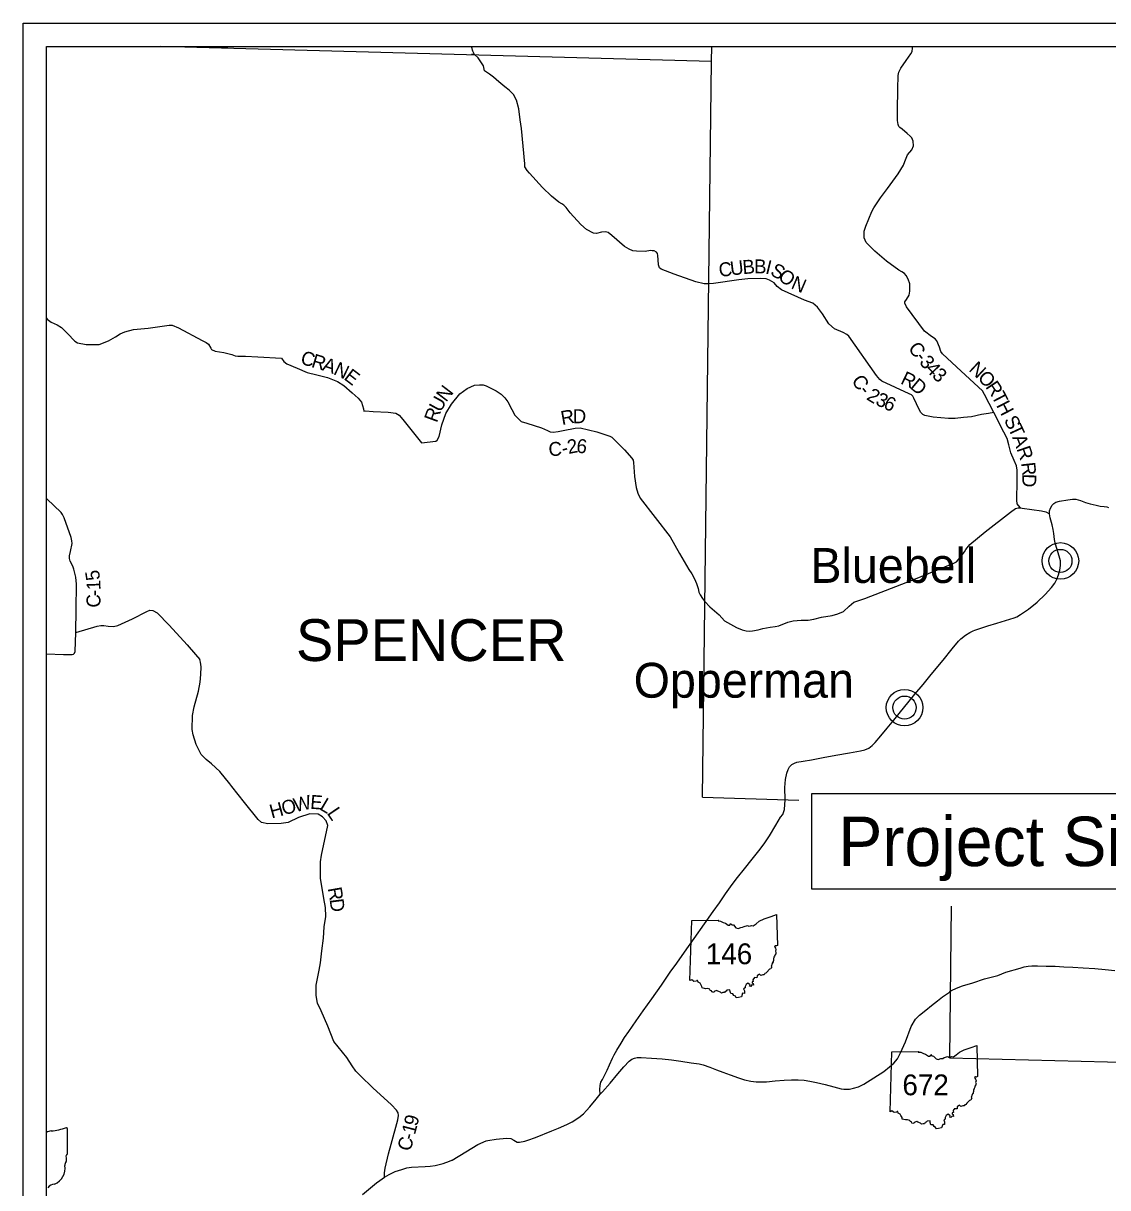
# Model space of a CAD drawing. Extents: x -452339 to 6403467, y -1 to 1814750.
# Drawn here: x -91226 to -67891, y 1630757 to 1655812 of the extents above; entities that cross this region are included whole.
import ezdxf

# ---------------------------------------------------------------- set-up
doc = ezdxf.new("R2010")
doc.units = 0
for name, color, linetype in [('Default', 7, 'Continuous'), ('GM_X_Adjacent_County_Text', 7, 'Continuous'), ('GM_X_County', 7, 'Continuous'), ('GM_X_County_Road', 7, 'Continuous'), ('GM_X_County_Road_Text', 7, 'Continuous'), ('GM_X_Section', 7, 'Continuous'), ('GM_X_Section_Text', 7, 'Continuous'), ('GM_X_Township_Road', 7, 'Continuous'), ('GM_X_Township_ROW', 7, 'Continuous'), ('GM_X_Township_Subdivision_Text', 7, 'Continuous')]:
    doc.layers.add(name, color=color, linetype=linetype)

msp = doc.modelspace()

# ---------------------------------------------------------------- linework, layer by layer
at = {"layer": 'Default'}
for p, q in [((-90726, 1655312), (-33348, 1655312)), ((-90726, 1597935), (-90726, 1655312)), ((-76880, 1635212), (-76838, 1636504)), ((-72575, 1632392), (-72533, 1633683))]:
    msp.add_line(p, q, dxfattribs=at)
msp.add_lwpolyline([(-91226, 1655812), (-32848, 1655812), (-32848, 1597435), (-91226, 1597435)], close=True, dxfattribs=at)
for points in [[(-76568, 1650204), (-76575, 1650204), (-76756, 1650252), (-77222, 1650415), (-77502, 1650519), (-77534, 1650553), (-77558, 1650617), (-77565, 1650721), (-77571, 1650817), (-77581, 1650857), (-77599, 1650889), (-77647, 1650914), (-77692, 1650918), (-77733, 1650920), (-77841, 1650900), (-78030, 1650907), (-78108, 1650917), (-78190, 1650950), (-78287, 1651008), (-78564, 1651243), (-78640, 1651312), (-78698, 1651326), (-78784, 1651318), (-78890, 1651290), (-78957, 1651299), (-79105, 1651373), (-79230, 1651484), (-79461, 1651733), (-79547, 1651845), (-79591, 1651896), (-79637, 1651930), (-79699, 1651962), (-79858, 1652094), (-80055, 1652282), (-80334, 1652589), (-80384, 1652644), (-80431, 1652724), (-80437, 1652786), (-80508, 1653547), (-80535, 1653738), (-80565, 1653970), (-80614, 1654155), (-80680, 1654279), (-80771, 1654370), (-80865, 1654444), (-80993, 1654549), (-81108, 1654653), (-81192, 1654720), (-81301, 1654788), (-81323, 1654893), (-81363, 1654963), (-81437, 1655072), (-81514, 1655141), (-81552, 1655212), (-81559, 1655236)], [(-73135, 1651262), (-73129, 1651340), (-73096, 1651448), (-72968, 1651760), (-72926, 1651840), (-72777, 1652055), (-72627, 1652257), (-72399, 1652572), (-72286, 1652758), (-72258, 1652838), (-72196, 1652983), (-72108, 1653091), (-72073, 1653173), (-72079, 1653275), (-72107, 1653345), (-72143, 1653381), (-72204, 1653440), (-72316, 1653532), (-72367, 1653570), (-72387, 1653588), (-72403, 1653633), (-72411, 1653717), (-72411, 1653933), (-72410, 1654405), (-72400, 1654689), (-72385, 1654761), (-72343, 1654847), (-72229, 1655011), (-72125, 1655156), (-72101, 1655206), (-72092, 1655276), (-72093, 1655312)], [(-69769, 1645384), (-69814, 1645433), (-69838, 1645471), (-69850, 1645551), (-69836, 1645967), (-69838, 1646197), (-69853, 1646289), (-69905, 1646403), (-69978, 1646571), (-70017, 1646742), (-70055, 1646876), (-70126, 1647012), (-70344, 1647439), (-70546, 1647828), (-70582, 1647900), (-70669, 1647980), (-71146, 1648418), (-71448, 1648699), (-71482, 1648753), (-71510, 1648842), (-71569, 1648982), (-71601, 1649020), (-71681, 1649072), (-71830, 1649189), (-72223, 1649710), (-72260, 1649793), (-72258, 1649819), (-72218, 1649872), (-72166, 1649964), (-72152, 1650050), (-72148, 1650118), (-72149, 1650206), (-72183, 1650308), (-72229, 1650385), (-72262, 1650427), (-72318, 1650467), (-72386, 1650503), (-72654, 1650694), (-72905, 1650909), (-73090, 1651096), (-73131, 1651194), (-73135, 1651262)], [(-70344, 1647439), (-70458, 1647417), (-70609, 1647392), (-70823, 1647345), (-70995, 1647327), (-71174, 1647308), (-71316, 1647311), (-71647, 1647336), (-71824, 1647372), (-71866, 1647393), (-71918, 1647447), (-72003, 1647625), (-72060, 1647743), (-72086, 1647788), (-72112, 1647814), (-72160, 1647840), (-72753, 1648112), (-72797, 1648148), (-72866, 1648237), (-73460, 1649081), (-73507, 1649119), (-73587, 1649157), (-73770, 1649238), (-73889, 1649347), (-74026, 1649563), (-74136, 1649706), (-74233, 1649790), (-74418, 1649857), (-74910, 1650080), (-75006, 1650148), (-75068, 1650225), (-75166, 1650285), (-75243, 1650311), (-75371, 1650323), (-75635, 1650314), (-75831, 1650293), (-76371, 1650216), (-76478, 1650204), (-76568, 1650204)], [(-90726, 1649464), (-90712, 1649446), (-90626, 1649379), (-90500, 1649321), (-90403, 1649266), (-90273, 1649138), (-90114, 1648969), (-90058, 1648937), (-89870, 1648899), (-89594, 1648904), (-89391, 1648977), (-89238, 1649064), (-89138, 1649127), (-89043, 1649170), (-88852, 1649221), (-88540, 1649251), (-88087, 1649317), (-88024, 1649314), (-87885, 1649257), (-87380, 1648987), (-87290, 1648944), (-87240, 1648908), (-87193, 1648824), (-87177, 1648794), (-87099, 1648760), (-86911, 1648727), (-86739, 1648682), (-86663, 1648655), (-86609, 1648651), (-86447, 1648648), (-86180, 1648636), (-85668, 1648603), (-85616, 1648537), (-85552, 1648485), (-85333, 1648390), (-85117, 1648299), (-84911, 1648248), (-84677, 1648190), (-84465, 1648105), (-84328, 1648018), (-84146, 1647860), (-84023, 1647745), (-83951, 1647657), (-83902, 1647515), (-83901, 1647465), (-83861, 1647470), (-83700, 1647458), (-83376, 1647444), (-83210, 1647421), (-83134, 1647380), (-83057, 1647284), (-82657, 1646782), (-82349, 1646823), (-82318, 1646842), (-82280, 1646924), (-82218, 1647169), (-82132, 1647419), (-82015, 1647616), (-81833, 1647840), (-81672, 1647957), (-81513, 1648022), (-81410, 1648034), (-81330, 1648034), (-81264, 1648014), (-81053, 1647905), (-80943, 1647832), (-80867, 1647756), (-80802, 1647664), (-80716, 1647501), (-80647, 1647381), (-80587, 1647313), (-80509, 1647244), (-80388, 1647208), (-80077, 1647105), (-79949, 1647048), (-79891, 1647020), (-79827, 1647014), (-79717, 1647027), (-79612, 1647051), (-79352, 1647100), (-79244, 1647110), (-78881, 1647022), (-78608, 1646931), (-78560, 1646903), (-78289, 1646636), (-78134, 1646457), (-78104, 1646413), (-78094, 1646359), (-78077, 1646058), (-78035, 1645822), (-78000, 1645702), (-77950, 1645591), (-77307, 1644765), (-77208, 1644582), (-77102, 1644402), (-76905, 1644057), (-76838, 1643963), (-76781, 1643858), (-76738, 1643756), (-76707, 1643650), (-76686, 1643574), (-76660, 1643511), (-76614, 1643438), (-76568, 1643378), (-76557, 1643367)], [(-90094, 1642705), (-90090, 1643198), (-90081, 1643742), (-90098, 1643891), (-90141, 1644063), (-90162, 1644133), (-90215, 1644236), (-90229, 1644294), (-90233, 1644354), (-90212, 1644449), (-90177, 1644621), (-90180, 1644673), (-90194, 1644747), (-90347, 1645169), (-90381, 1645243), (-90414, 1645287), (-90721, 1645577), (-90726, 1645582)], [(-76557, 1643367), (-76453, 1643259), (-76249, 1643081), (-76140, 1642951), (-75880, 1642809), (-75758, 1642760), (-75670, 1642736), (-75609, 1642732), (-75538, 1642738), (-75410, 1642762), (-75313, 1642789), (-75156, 1642819), (-75050, 1642832), (-74971, 1642848), (-74776, 1642923), (-74660, 1642954), (-74490, 1642971), (-74335, 1642971), (-74217, 1642991), (-74047, 1643032), (-73823, 1643072), (-73701, 1643105), (-73579, 1643158), (-73457, 1643268), (-73356, 1643353), (-73120, 1643437), (-72098, 1643833), (-71201, 1644192), (-71145, 1644227), (-71067, 1644317), (-70976, 1644442), (-70941, 1644491), (-70858, 1644598), (-70530, 1644869), (-69986, 1645291), (-69872, 1645371), (-69817, 1645387), (-69769, 1645384)], [(-69769, 1645384), (-69735, 1645382), (-69316, 1645321)], [(-69316, 1645321), (-69314, 1645321), (-69223, 1645298), (-69144, 1645260)], [(-90726, 1642243), (-90360, 1642231), (-90231, 1642230), (-90177, 1642232), (-90145, 1642240), (-90123, 1642258), (-90107, 1642298), (-90094, 1642705), (-89636, 1642838), (-89558, 1642854), (-89496, 1642851), (-89396, 1642843), (-89282, 1642832), (-89191, 1642853), (-88878, 1642997), (-88566, 1643155), (-88502, 1643181), (-88438, 1643177), (-88346, 1643130), (-88086, 1642859), (-87702, 1642437), (-87523, 1642231), (-87426, 1642126)], [(-83456, 1630983), (-83456, 1631075), (-83442, 1631179), (-83364, 1631488), (-83309, 1631695), (-83164, 1632214), (-83154, 1632311), (-83161, 1632369), (-83194, 1632424), (-83301, 1632537), (-83705, 1632907), (-83969, 1633163), (-84070, 1633268), (-84148, 1633376), (-84262, 1633559), (-84541, 1633902), (-84676, 1634231), (-84818, 1634563), (-84898, 1634726), (-84927, 1634894), (-84927, 1635114), (-84859, 1635440), (-84831, 1635599), (-84802, 1635851), (-84767, 1636127), (-84748, 1636371), (-84715, 1636596), (-84721, 1636787), (-84759, 1636983), (-84831, 1637414), (-84833, 1637584), (-84829, 1637766), (-84806, 1637912), (-84670, 1638551), (-84711, 1638653), (-84784, 1638738), (-84879, 1638791), (-85062, 1638801), (-85307, 1638720), (-85524, 1638613), (-85680, 1638591), (-85967, 1638583), (-86099, 1638612), (-86172, 1638679), (-86469, 1639049), (-86735, 1639392), (-86780, 1639449), (-87000, 1639716), (-87178, 1639880), (-87294, 1639973), (-87397, 1640079), (-87506, 1640294), (-87570, 1640499), (-87594, 1640617), (-87581, 1640921), (-87546, 1641107), (-87457, 1641440), (-87418, 1641637), (-87404, 1641801), (-87400, 1641965), (-87415, 1642066), (-87426, 1642126)], [(-76838, 1636504), (-76266, 1636512), (-76275, 1636496), (-76221, 1636493), (-76164, 1636465), (-76115, 1636448), (-76056, 1636407), (-76020, 1636407), (-76005, 1636441), (-75978, 1636415), (-75946, 1636411), (-75890, 1636349), (-75844, 1636335), (-75788, 1636357), (-75747, 1636360), (-75717, 1636381), (-75639, 1636399), (-75616, 1636388), (-75575, 1636391), (-75554, 1636398), (-75518, 1636391), (-75454, 1636438), (-75388, 1636493), (-75287, 1636546), (-75136, 1636595), (-75017, 1636639), (-74999, 1635969)], [(-74999, 1635969), (-75017, 1635960), (-75044, 1635964), (-75063, 1635946), (-75040, 1635914), (-75029, 1635881), (-75039, 1635845), (-75029, 1635815), (-75036, 1635789), (-75053, 1635764), (-75059, 1635740), (-75074, 1635715), (-75073, 1635701), (-75086, 1635690), (-75084, 1635648), (-75091, 1635625), (-75088, 1635605), (-75111, 1635600), (-75106, 1635583), (-75121, 1635570), (-75117, 1635548), (-75134, 1635534), (-75118, 1635506), (-75131, 1635497), (-75141, 1635463), (-75171, 1635456), (-75228, 1635394), (-75249, 1635370), (-75272, 1635364), (-75285, 1635340), (-75313, 1635340), (-75356, 1635323), (-75384, 1635352), (-75433, 1635317), (-75438, 1635276), (-75500, 1635278), (-75498, 1635257), (-75511, 1635252), (-75524, 1635231), (-75517, 1635195), (-75545, 1635186), (-75542, 1635165), (-75523, 1635152), (-75515, 1635112), (-75546, 1635120), (-75571, 1635086), (-75597, 1635094), (-75588, 1635122), (-75632, 1635157), (-75673, 1635130), (-75695, 1635085), (-75695, 1635055), (-75726, 1635037), (-75706, 1634996), (-75710, 1634967), (-75709, 1634939), (-75747, 1634940), (-75771, 1634866)], [(-75771, 1634866), (-75838, 1634852), (-75884, 1634843), (-75900, 1634877), (-75933, 1634895), (-75955, 1634928), (-76003, 1634933), (-76014, 1634980), (-76019, 1635017), (-76084, 1635008), (-76102, 1634985), (-76125, 1634979), (-76139, 1634956), (-76170, 1634954), (-76204, 1634943), (-76226, 1634965), (-76281, 1634988), (-76306, 1635000), (-76359, 1634982), (-76369, 1634960), (-76411, 1634970), (-76420, 1634994), (-76445, 1635001), (-76451, 1635027), (-76505, 1635041), (-76546, 1635035), (-76618, 1635056), (-76623, 1635090), (-76647, 1635131), (-76659, 1635160), (-76705, 1635181), (-76715, 1635215), (-76729, 1635215), (-76743, 1635201), (-76794, 1635194), (-76814, 1635208), (-76842, 1635232), (-76880, 1635212)], [(-72533, 1633683), (-71961, 1633691), (-71969, 1633676), (-71916, 1633672), (-71858, 1633645), (-71810, 1633628), (-71751, 1633587), (-71715, 1633587), (-71700, 1633621), (-71673, 1633595), (-71640, 1633590), (-71584, 1633528), (-71538, 1633515), (-71483, 1633536), (-71442, 1633539), (-71412, 1633560), (-71333, 1633578), (-71311, 1633567), (-71270, 1633570), (-71249, 1633578), (-71212, 1633571), (-71149, 1633618), (-71083, 1633673), (-70982, 1633725), (-70831, 1633774), (-70711, 1633819), (-70694, 1633149)], [(-70694, 1633149), (-70712, 1633139), (-70739, 1633144), (-70758, 1633125), (-70735, 1633094), (-70724, 1633060), (-70734, 1633024), (-70724, 1632994), (-70730, 1632969), (-70748, 1632943), (-70754, 1632920), (-70768, 1632894), (-70767, 1632880), (-70781, 1632870), (-70779, 1632827), (-70786, 1632804), (-70783, 1632784), (-70806, 1632779), (-70801, 1632762), (-70815, 1632749), (-70812, 1632728), (-70829, 1632713), (-70813, 1632685), (-70825, 1632676), (-70836, 1632642), (-70865, 1632635), (-70923, 1632573), (-70944, 1632549), (-70967, 1632543), (-70980, 1632519), (-71008, 1632519), (-71051, 1632502), (-71079, 1632531), (-71128, 1632496), (-71133, 1632456), (-71194, 1632457), (-71192, 1632437), (-71206, 1632431), (-71218, 1632411), (-71211, 1632374), (-71240, 1632365), (-71237, 1632344), (-71218, 1632331), (-71210, 1632291), (-71240, 1632299), (-71265, 1632265), (-71292, 1632273), (-71283, 1632302), (-71327, 1632337), (-71368, 1632309), (-71389, 1632265), (-71390, 1632235), (-71421, 1632217), (-71401, 1632175), (-71405, 1632146), (-71404, 1632118), (-71442, 1632120), (-71466, 1632045)], [(-71466, 1632045), (-71532, 1632031), (-71578, 1632023), (-71595, 1632056), (-71628, 1632074), (-71650, 1632108), (-71697, 1632112), (-71709, 1632159), (-71714, 1632197), (-71779, 1632188), (-71797, 1632165), (-71820, 1632158), (-71833, 1632135), (-71865, 1632133), (-71899, 1632122), (-71921, 1632145), (-71976, 1632168), (-72001, 1632180), (-72053, 1632161), (-72064, 1632140), (-72105, 1632149), (-72115, 1632173), (-72140, 1632181), (-72146, 1632206), (-72199, 1632220), (-72241, 1632215), (-72313, 1632235), (-72317, 1632269), (-72342, 1632311), (-72354, 1632339), (-72400, 1632361), (-72409, 1632395), (-72424, 1632394), (-72437, 1632380), (-72488, 1632374), (-72508, 1632388), (-72537, 1632412), (-72575, 1632392)]]:
    msp.add_lwpolyline(points, dxfattribs=at)
at = {"layer": 'GM_X_County_Road'}
for points in [[(-78813, 1632767), (-78822, 1632869), (-78815, 1632955), (-78795, 1633025), (-78764, 1633088), (-78663, 1633285), (-78612, 1633404), (-78546, 1633546), (-78512, 1633617), (-78453, 1633713), (-78361, 1633870), (-78288, 1633990), (-78194, 1634121), (-78037, 1634346), (-77888, 1634563), (-77703, 1634821), (-77495, 1635116), (-77304, 1635394), (-77165, 1635586), (-77000, 1635828), (-76793, 1636119), (-76571, 1636436), (-76380, 1636703), (-76248, 1636887), (-76112, 1637079), (-75973, 1637279), (-75855, 1637432), (-75707, 1637616), (-75543, 1637825), (-75397, 1638005), (-75281, 1638156), (-75167, 1638330), (-75036, 1638556), (-74934, 1638727), (-74883, 1638788), (-74848, 1638895), (-74831, 1639105), (-74836, 1639370), (-74824, 1639544), (-74796, 1639675), (-74769, 1639755), (-74735, 1639814), (-74686, 1639862), (-74634, 1639893), (-74580, 1639912), (-74445, 1639935), (-74267, 1639967), (-74011, 1640014), (-73738, 1640064), (-73446, 1640117), (-73213, 1640158), (-73117, 1640181), (-73033, 1640216), (-72958, 1640269), (-72893, 1640338), (-72770, 1640482), (-72640, 1640642), (-72494, 1640816), (-72347, 1640998), (-72189, 1641190), (-72039, 1641376), (-71865, 1641584), (-71718, 1641766), (-71584, 1641930), (-71434, 1642108), (-71237, 1642351), (-71102, 1642515), (-71049, 1642570), (-70950, 1642643), (-70855, 1642704), (-70783, 1642741), (-70750, 1642753), (-70689, 1642774), (-70470, 1642847), (-70275, 1642901), (-69994, 1642987), (-69902, 1643018), (-69846, 1643041), (-69769, 1643090), (-69596, 1643208), (-69408, 1643356), (-69238, 1643521), (-69104, 1643670), (-69031, 1643768), (-68984, 1643850), (-68949, 1643941), (-68920, 1644043), (-68905, 1644142), (-68909, 1644244), (-68934, 1644346), (-68994, 1644531), (-69025, 1644635), (-69036, 1644705), (-69048, 1644837), (-69065, 1644921), (-69090, 1645019), (-69130, 1645171), (-69144, 1645260), (-69142, 1645321), (-69125, 1645381), (-69089, 1645440), (-69054, 1645482), (-69008, 1645505), (-68928, 1645528), (-68747, 1645558), (-68649, 1645575), (-68575, 1645572), (-68474, 1645541), (-68368, 1645500), (-68271, 1645471), (-68139, 1645441), (-68055, 1645424), (-67970, 1645415), (-67912, 1645406), (-67876, 1645392)], [(-78813, 1632767), (-78759, 1632820), (-78596, 1633007), (-78434, 1633204), (-78301, 1633357), (-78189, 1633478), (-78133, 1633524), (-78077, 1633547), (-78017, 1633557), (-77929, 1633557), (-77711, 1633541), (-77476, 1633528), (-77274, 1633509), (-77077, 1633480), (-76851, 1633447), (-76684, 1633421), (-76596, 1633400), (-76454, 1633348), (-76307, 1633291), (-76175, 1633244), (-76014, 1633184), (-75838, 1633121), (-75709, 1633080), (-75571, 1633046), (-75455, 1633033), (-75344, 1633033), (-75232, 1633038), (-75046, 1633055), (-74856, 1633070), (-74693, 1633080), (-74553, 1633079), (-74421, 1633068), (-74301, 1633052), (-74156, 1633019), (-73972, 1632978), (-73785, 1632931), (-73629, 1632887), (-73568, 1632880), (-73539, 1632876), (-73448, 1632880), (-73358, 1632899), (-73252, 1632931), (-73142, 1632988), (-72712, 1633260), (-72588, 1633358), (-72493, 1633440), (-72411, 1633527), (-72347, 1633662), (-72242, 1633895), (-72118, 1634223), (-72026, 1634386), (-71940, 1634473), (-71802, 1634578), (-71680, 1634679), (-71555, 1634781), (-71444, 1634861), (-71299, 1634968), (-71286, 1634978), (-71226, 1635014), (-71111, 1635064), (-71019, 1635098), (-70790, 1635166), (-70542, 1635252), (-70254, 1635324), (-70086, 1635398), (-69772, 1635482), (-69688, 1635507), (-69604, 1635521), (-69526, 1635530), (-69399, 1635528), (-69217, 1635527), (-69019, 1635522), (-68838, 1635513), (-68642, 1635500), (-68416, 1635489), (-68171, 1635472), (-67945, 1635453), (-67740, 1635432)], [(-79108, 1632418), (-79036, 1632497), (-78895, 1632660), (-78813, 1632767)], [(-81995, 1631352), (-81706, 1631528), (-81444, 1631686), (-81267, 1631766), (-81229, 1631776), (-81047, 1631800), (-80826, 1631821), (-80736, 1631814), (-80670, 1631782), (-80596, 1631736), (-80550, 1631734), (-80434, 1631762), (-80366, 1631780), (-80201, 1631839), (-79854, 1631980), (-79710, 1632041), (-79529, 1632115), (-79413, 1632172), (-79268, 1632270), (-79169, 1632350), (-79108, 1632418)], [(-83927, 1630614), (-83625, 1630865), (-83554, 1630914), (-83456, 1630983), (-83351, 1631042), (-83222, 1631104), (-83077, 1631150), (-82974, 1631184), (-82870, 1631201), (-82581, 1631212), (-82473, 1631221), (-82361, 1631237), (-82193, 1631277), (-82057, 1631328), (-82003, 1631347), (-81995, 1631352)]]:
    msp.add_lwpolyline(points, dxfattribs=at)
at = {"layer": 'GM_X_County_Road_Text'}
for centre, radius in [((-68909, 1644244), 393), ((-68909, 1644244), 249), ((-72263, 1641087), 393), ((-72263, 1641087), 249)]:
    msp.add_circle(centre, radius, dxfattribs=at)
at = {"layer": 'GM_X_Section'}
msp.add_lwpolyline([(-81559, 1655236), (-81569, 1655272), (-81578, 1655312)], dxfattribs=at)
at = {"layer": 'GM_X_Section_Text'}
for p, q in [((-76414, 1654991), (-88282, 1655312)), ((-86826, 1655275), (-87243, 1655297)), ((-81514, 1655141), (-81578, 1655140)), ((-76414, 1654991), (-76411, 1655312)), ((-76609, 1639158), (-76414, 1654991)), ((-76609, 1639158), (-74539, 1639098)), ((-71263, 1636815), (-71296, 1633554)), ((-71296, 1633554), (-65969, 1633411))]:
    msp.add_line(p, q, dxfattribs=at)
at = {"layer": 'GM_X_Township_Road'}
for p in [(-90281, 1632032), (-90281, 1631479)]:
    msp.add_line(p, (-90281, 1631479), dxfattribs=at)
for centre, radius, start, end in [((-90588, 1631683), 297, 97.3462, 117.5636), ((-90777, 1633446), 1476, 275.8445, 288.9065), ((-90296, 1632034), 15.5, 351.8621, 97.738), ((-90284, 1631438), 24, 107.944, 210.337), ((-90437, 1631368), 144, 340.033, 23.6496), ((-90297, 1631477), 16.6, 289.6038, 7.7341), ((-90694, 1631177), 369, 292.3089, 8.9858), ((-90225, 1631248), 105, 136.8065, 186.9296), ((-90538, 1630634), 202, 94.4031, 142.5768)]:
    msp.add_arc(centre, radius, start, end, dxfattribs=at)
at = {"layer": 'GM_X_Township_ROW'}
for p, q in [((-74256, 1639239), (-64016, 1639239)), ((-64016, 1637179), (-74256, 1637179))]:
    msp.add_line(p, q, dxfattribs=at)
msp.add_lwpolyline([(-74256, 1637179), (-74256, 1639239)], dxfattribs=at)

# ---------------------------------------------------------------- texts
at = {"layer": 'Default'}
for s, p in [('146', (-76540, 1635566)), ('672', (-72309, 1632746))]:
    msp.add_text(s, height=447.7, dxfattribs=at).set_placement(p)
at = {"layer": 'GM_X_Adjacent_County_Text'}
for s, p in [('Bluebell', (-74288, 1643771)), ('Opperman', (-78091, 1641301))]:
    msp.add_text(s, height=750, rotation=0, dxfattribs=at).set_placement(p)
at = {"layer": 'GM_X_County'}
for s, rotation, p in [('C', 7.1652, (-76243, 1650352)), ('U', 6.9732, (-75999, 1650383)), ('B', 4.2444, (-75740, 1650414)), ('B', 359.237, (-75502, 1650433)), ('I', 346.102, (-75273, 1650432)), ('S', 331.2181, (-75173, 1650409)), ('O', 322.1589, (-75006, 1650319)), ('N', 336.9026, (-74725, 1650114)), ('C', 307.9613, (-72199, 1648814)), ('C', 343.1209, (-85280, 1648491)), ('R', 343.0735, (-85044, 1648420)), ('-', 308.7266, (-72045, 1648617)), ('3', 310.7532, (-71960, 1648512)), ('A', 341.6739, (-84810, 1648349)), ('N', 334.4728, (-84569, 1648270)), ('E', 322.5644, (-84345, 1648164)), ('4', 313.5815, (-71829, 1648360)), ('3', 317.0709, (-71687, 1648212)), ('N', 316.989, (-70896, 1648347)), ('C', 304.568, (-73416, 1648121)), ('R', 334.4718, (-72368, 1648067)), ('D', 320.2555, (-72162, 1647972)), ('O', 313.6875, (-70706, 1648170)), ('R', 303.6814, (-70532, 1647990)), ('N', 52.6693, (-82127, 1647646)), ('-', 309.207, (-73260, 1647897)), ('2', 328.4987, (-73100, 1647729)), ('T', 297.6384, (-70400, 1647792)), ('U', 61.1593, (-82248, 1647425)), ('3', 335.3777, (-72907, 1647614)), ('6', 335.6382, (-72738, 1647536)), ('H', 297.3536, (-70296, 1647594)), ('R', 69.8251, (-82328, 1647204)), ('R', 10.2432, (-79632, 1647166)), ('D', 359.5374, (-79404, 1647208)), ('S', 297.211, (-70132, 1647277)), ('T', 294.8859, (-70041, 1647100)), ('2', 10.7277, (-79493, 1646544)), ('6', 353.0512, (-79335, 1646578)), ('A', 290.4484, (-69949, 1646902)), ('C', 2.2564, (-79919, 1646498)), ('-', 13.5328, (-79609, 1646516)), ('R', 288.846, (-69857, 1646657)), ('R', 276.4182, (-69754, 1646353)), ('D', 269.224, (-69726, 1646118)), ('5', 98.6347, (-89570, 1643845)), ('1', 91.0114, (-89563, 1643616)), ('C', 89.5238, (-89566, 1643238)), ('-', 89.7759, (-89564, 1643486)), ('O', 15.3077, (-85625, 1638768)), ('W', 12.7639, (-85374, 1638836)), ('E', 355.8094, (-85059, 1638912)), ('L', 329.3626, (-84869, 1638906)), ('H', 15.3104, (-85880, 1638698)), ('L', 304.0051, (-84702, 1638816)), ('R', 280.0706, (-84677, 1637200)), ('D', 277.1474, (-84635, 1636961)), ('1', 75.274, (-82799, 1631884)), ('9', 76.11, (-82751, 1632067)), ('C', 75.0749, (-82894, 1631526)), ('-', 75.1213, (-82830, 1631764))]:
    msp.add_text(s, height=300, rotation=rotation, dxfattribs=at).set_placement(p)
at = {"layer": 'GM_X_Township_ROW'}
msp.add_text('Project Site', height=1063.82, dxfattribs=at).set_placement((-73689, 1637677))
at = {"layer": 'GM_X_Township_Subdivision_Text'}
msp.add_text('SPENCER', height=900, rotation=0, dxfattribs=at).set_placement((-85357, 1642090))

doc.saveas('drawing.dxf')
